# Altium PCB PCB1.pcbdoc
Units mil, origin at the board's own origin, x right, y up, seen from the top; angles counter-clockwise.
Board outline 1259.84 x 1771.65 mil, 2 copper layers (Top Layer, Bottom Layer), stack 62.206 mil thick; 37 components, 23 nets, 173 pads, 119 vias.
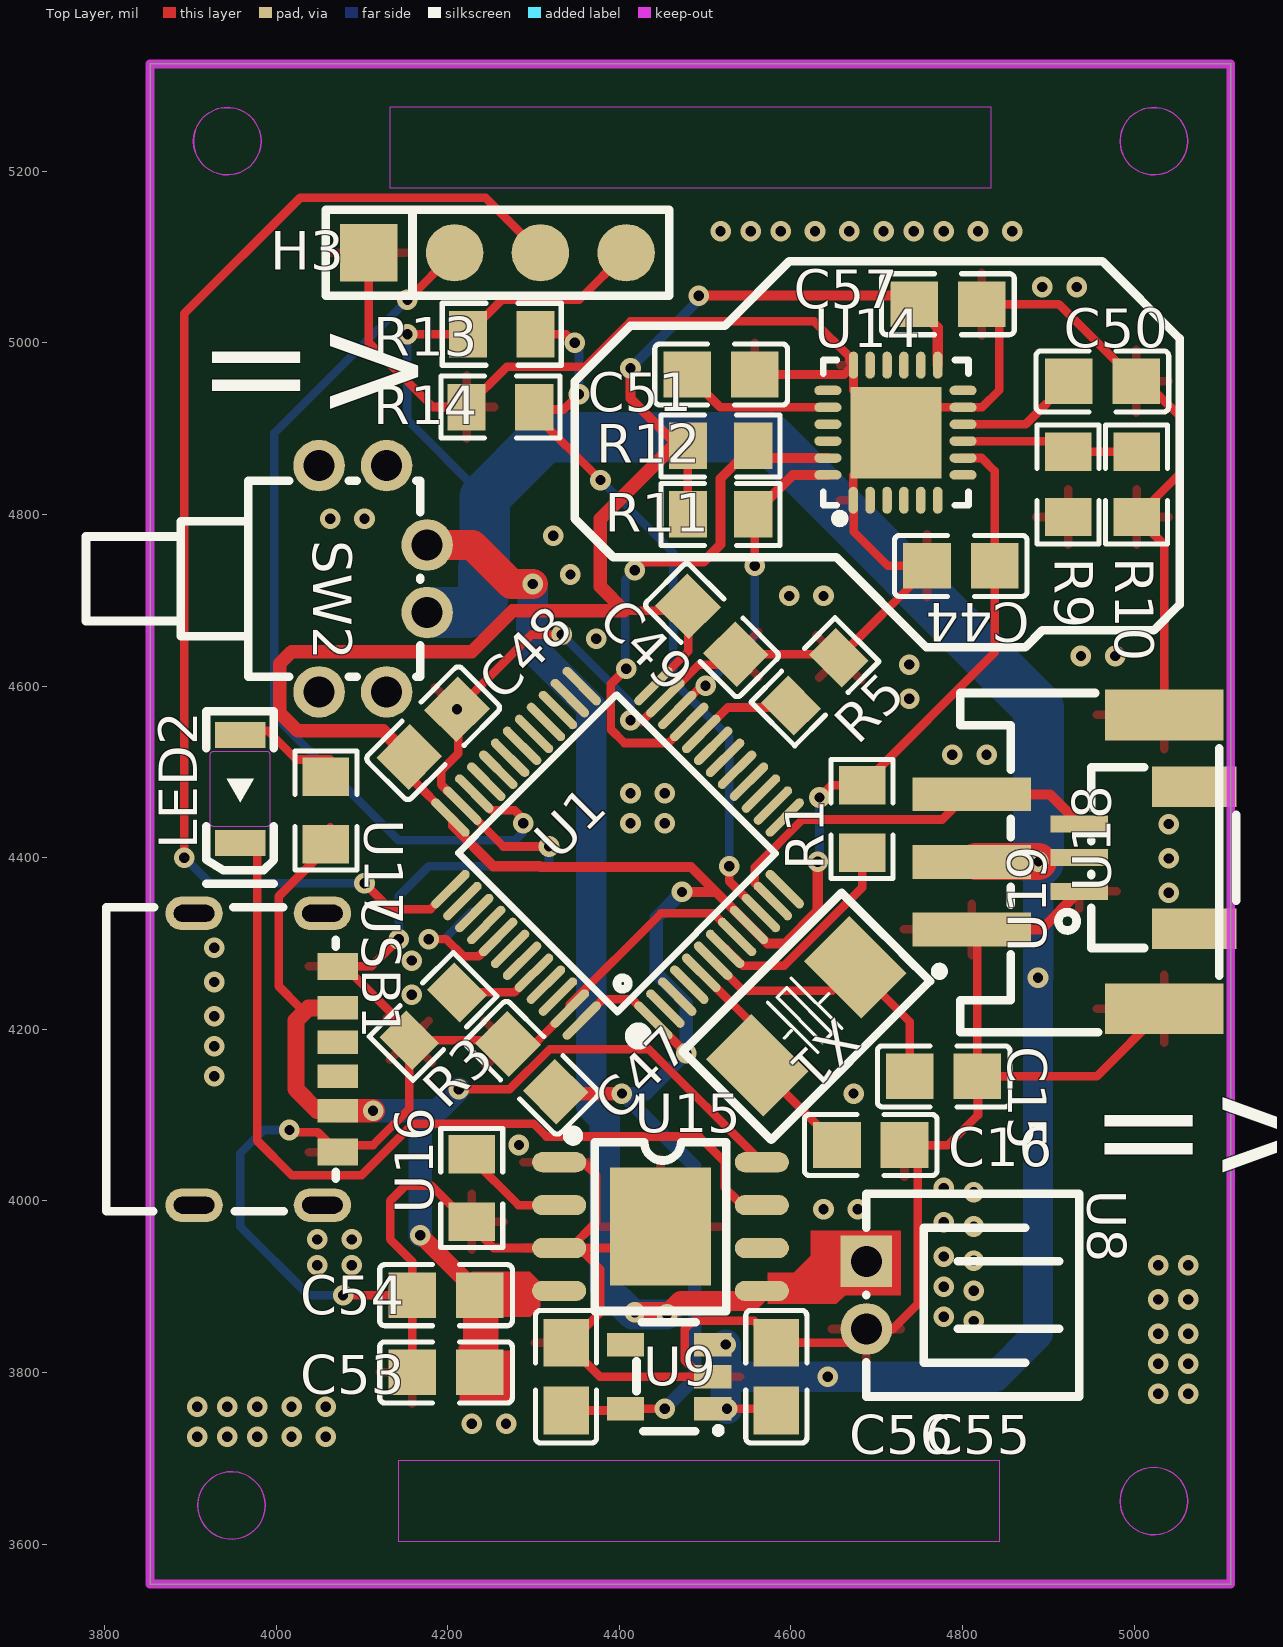
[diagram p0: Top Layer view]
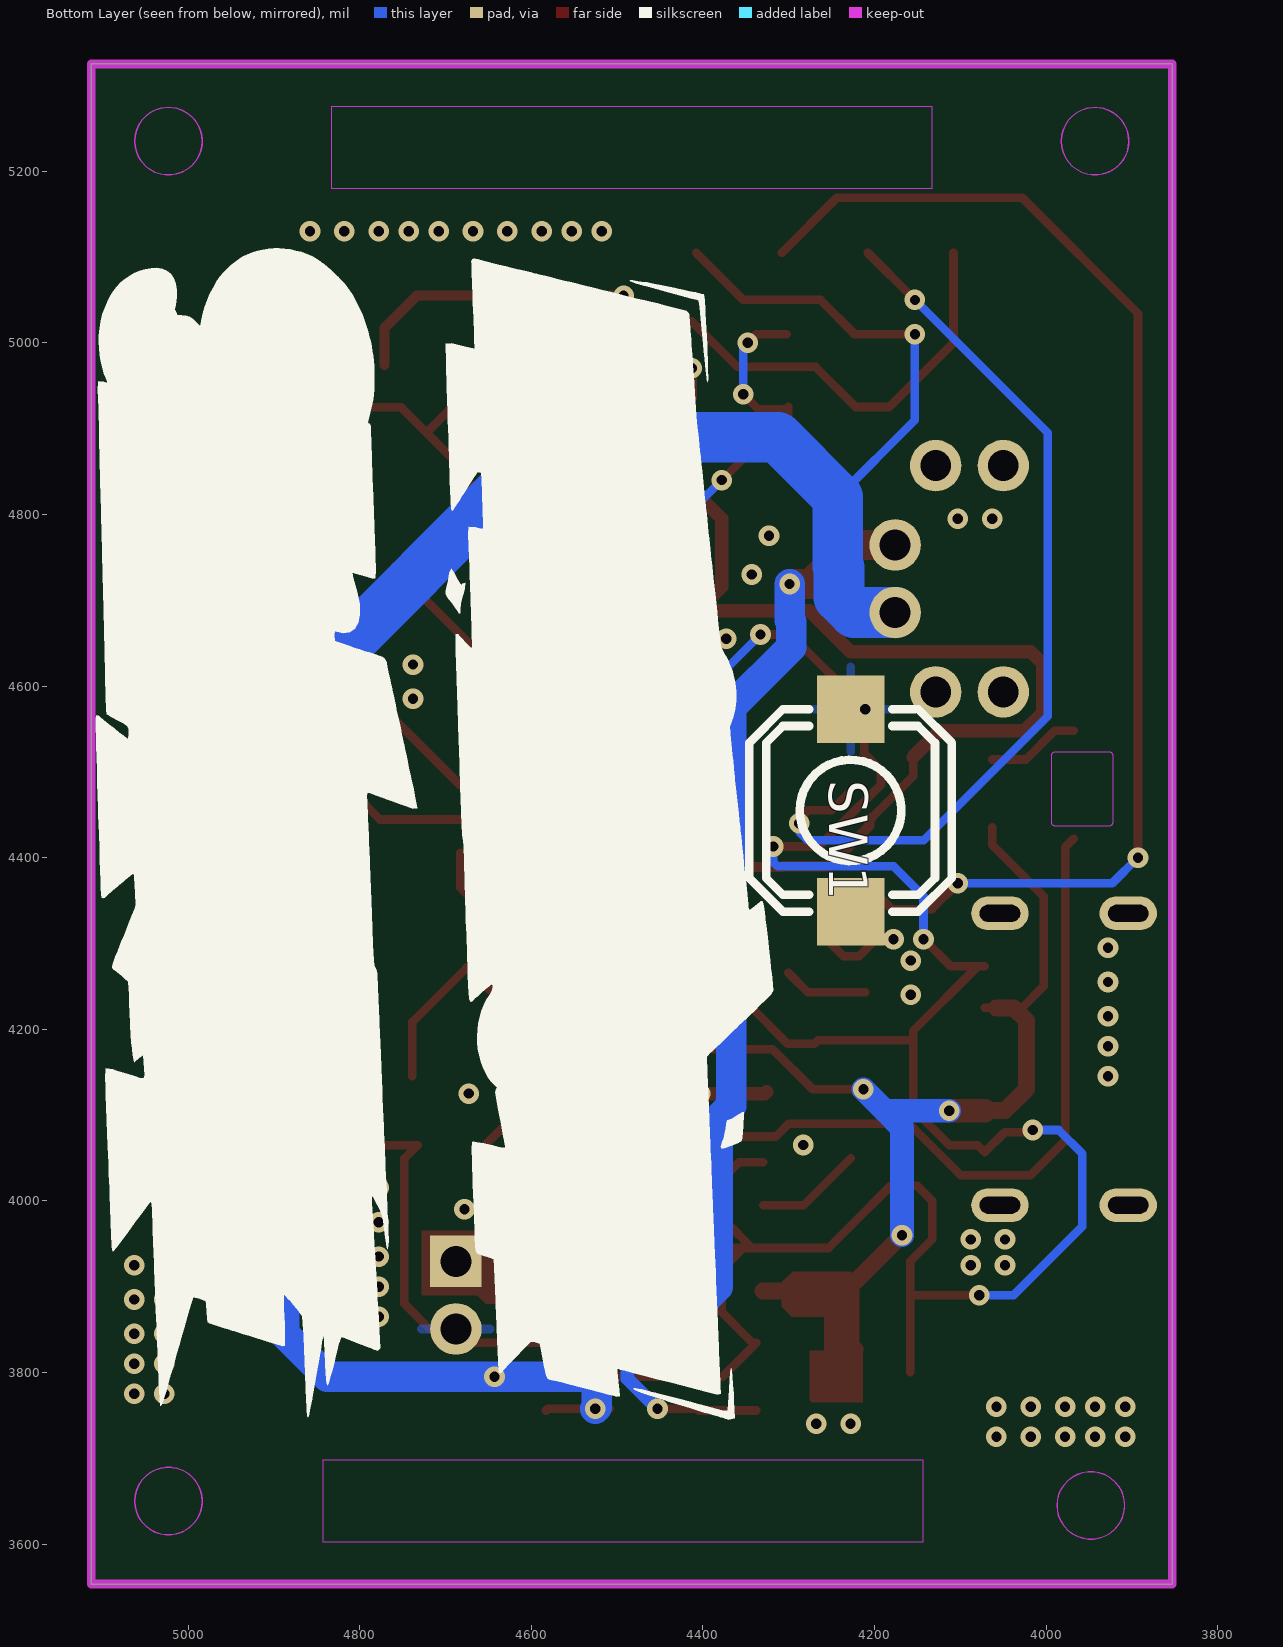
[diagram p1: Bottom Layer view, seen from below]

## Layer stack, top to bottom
Top Solder Mask Layer: solder mask 0.394, Dk 3.3
Top Layer: signal copper 1.379
Dielectric1: surface 59.449, FR4, Dk 4.5
Bottom Layer: signal copper 1.378
Bottom Solder Mask Layer: solder mask 0.394, Dk 3.3

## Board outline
3852.95,5325 5112.8,5325 5112.8,3553.35 3852.95,3553.35

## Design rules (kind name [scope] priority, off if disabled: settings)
BoardOutlineClearance copperThickness1oz [All] p0: genericclearance=10 ignorepadtopadclearanceinfootprint=FALSE except(0: Arc-SplitContinuation Track-SplitContinuation SMDPad-SplitContinuation THPad-SplitContinuation Via-SplitContinuation Fill-SplitContinuation Poly-SplitContinuation Region-SplitContinuation Text-SplitContinuation)
BoardOutlineClearance copperThickness2oz [All] p0: genericclearance=10 ignorepadtopadclearanceinfootprint=FALSE except(0: Arc-SplitContinuation Track-SplitContinuation SMDPad-SplitContinuation THPad-SplitContinuation Via-SplitContinuation Fill-SplitContinuation Poly-SplitContinuation Region-SplitContinuation Text-SplitContinuation)
BoardOutlineClearance Plane_innerPlane [All] p0: genericclearance=10 ignorepadtopadclearanceinfootprint=FALSE except(0: Arc-SplitContinuation Track-SplitContinuation SMDPad-SplitContinuation THPad-SplitContinuation Via-SplitContinuation Fill-SplitContinuation Poly-SplitContinuation Region-SplitContinuation Text-SplitContinuation)
BoardOutlineClearance Copper_copperRegion [All] p0: genericclearance=10 ignorepadtopadclearanceinfootprint=FALSE except(0: Arc-SplitContinuation Track-SplitContinuation SMDPad-SplitContinuation THPad-SplitContinuation Via-SplitContinuation Fill-SplitContinuation Poly-SplitContinuation Region-SplitContinuation Text-SplitContinuation)
BoardOutlineClearance otherClearance [All] p0: genericclearance=10 ignorepadtopadclearanceinfootprint=FALSE except(0: Arc-SplitContinuation Track-SplitContinuation SMDPad-SplitContinuation THPad-SplitContinuation Via-SplitContinuation Fill-SplitContinuation Poly-SplitContinuation Region-SplitContinuation Text-SplitContinuation)
Clearance copperThickness1oz [All] p1: gap=7 ignorepadtopadclearanceinfootprint=FALSE
Clearance copperThickness2oz [All] p1: gap=7 ignorepadtopadclearanceinfootprint=FALSE
Clearance Plane_innerPlane [All] p1: gap=7 ignorepadtopadclearanceinfootprint=FALSE
Clearance Copper_copperRegion [All] p1: gap=7 ignorepadtopadclearanceinfootprint=FALSE
Clearance otherClearance [All] p1: gap=7 ignorepadtopadclearanceinfootprint=FALSE
DiffPairsRouting differentialPair [All] p1: maxuncoupledlength=10 minlimit=6 maxlimit=Infinity mostfreqgap=6 toplayer_minwidth=5 toplayer_prefwidth=10 toplayer_maxwidth=100 bottomlayer_minwidth=5 bottomlayer_prefwidth=10 bottomlayer_maxwidth=100
PasteMaskExpansion pasteMaskExpansion [All] p1: expansion=0
PlaneConnect innerPlane [All] p1: planeconnectstyle=Relief reliefexpansion=20 reliefentries=4 reliefconductorwidth=10 reliefairgap=10
PolygonConnect copperRegion [All] p1: connectstyle=Relief reliefentries=4 reliefconductorwidth=10 polygonreliefangle="90 Angle" airgapwidth=10
RoutingVias viaSize [All] p1: viastyle="Through Hole" holewidth=12.0078 minholewidth=11.811 maxholewidth=248.0314 width=12.0078 minwidth=11.811 maxwidth=248.0314
SolderMaskExpansion solderMaskExpansion [All] p1: useseparateexpansions=TRUE expansion=2 expansionbottom=2
Width copperThickness1oz [All] p1: maxlimit=100 minlimit=5 preferedwidth=10
Width copperThickness2oz [All] p1: maxlimit=100 minlimit=8 preferedwidth=10

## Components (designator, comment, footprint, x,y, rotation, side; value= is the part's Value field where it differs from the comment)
C15 "" C0805 4777.95,4145 r180 top
C16 "" C0805 4692.95,4065 r180 top
C44 "" C0603 4797.95,4740 r180 top
C47 "" C0805 4297.95,4155 r315 top
C48 "" C0805 4182.95,4545 r225 top
C49 "" C0805 4507.95,4665 r135 top
C50 "" C0805 4962.95,4955 r180 top
C51 "" C0805 4518.62,4963.09 r0 top
C53 "" C0805 4197.95,3800 r0 top
C54 "" C0805 4197.95,3890 r0 top
C55 "" C0805 4582.95,3795 r270 top
C56 "" C0805 4337.95,3795 r270 top
C57 "" C0805 4782.95,5045 r180 top
H3 "" HDR-TH_4P-P2.54-V-M 4257.95,5105 r0 top
LED2 "" LED1206-FD_GREEN-EH 3957.95,4480 r270 top
R1 "" 0603R 4682.95,4445 r90 top
R3 "" 0603R 4182.95,4215 r225 top
R5 "" 0603R 4627.95,4605 r45 top
R9 "" R0603 4922.95,4835 r270 top
R10 "" R0603 5002.95,4835 r270 top
R11 "" R0603 4517.95,4800 r0 top
R12 "" R0603 4517.95,4880 r0 top
R13 "" R0805 4262.95,5010 r180 top
R14 "" R0805 4261.29,4925.15 r0 top
SW1 "" SW-SMD_L6.0-W6.0-P6.00-LS6.8 4227.95,4455 r270 bottom
SW2 "" SW-TH_TK-6580A-1 4112.95,4725 r270 top
U1 "" LQFP-48_L7.0-W7.0-P0.50-LS9.0-BL 4397.95,4405 r45 top
U8 "" CONN-TH_2P-P2.00_GP01-2001WR-2P 4687.95,3890 r270 top
U9 "" TSOT-23-5_L2.9-W1.6-P0.95-LS2.8-BR 4457.95,3795 r0 top
U14 "" QFN-24_L4.0-W4.0-P0.50-BL-EP2.7 4721.79,4895.24 r0 top
U15 "" SOP-8_L4.9-W3.9-P1.27-LS6.0-TL-EP 4447.95,3970 r0 top
U16 "" R0805 4227.95,4015 r90 top
U17 "" R0805 4057.95,4455 r90 top
U18 "" CONN-SMD_3P-P2.00_XUNPU_WAFER-PH2.0-3PWB 4922.95,4395 r90 top
U19 "" CONN-SMD_3P-P1.00_WAFER-SH1.0-3PWB 5002.95,4400 r90 top
USB1 "" TYPE-C-SMD_TYPE-C-6P-073 3987.95,4165 r270 top
X1 "" OSC-SMD_L5.0-W3.2 4617.95,4215 r225 top

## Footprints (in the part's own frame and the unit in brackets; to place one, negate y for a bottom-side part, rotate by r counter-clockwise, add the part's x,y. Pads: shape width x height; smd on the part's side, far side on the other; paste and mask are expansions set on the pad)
0603R [mm]
  rect 1.133x1.377 smd: 1(-1,0) 2(1,0)
  silkscreen extent -1.76,-0.92 1.76,0.92
C0603 [mm]
  rect 1.41x1.35 smd: 1(-1,0) 2(1,0)
  silkscreen extent -1.96,-0.9 1.96,0.9
C0805 [mm]
  rect 1.41x1.35 smd: 1(-1,0) 2(1,0)
  silkscreen extent -1.96,-0.9 1.96,0.9
CONN-SMD_3P-P1.00_WAFER-SH1.0-3PWB [mm]
  rect 0.5x1.7 smd: 1(-1,1.7) 2(0,1.7) 3(1,1.7)
  rect 1.2x2.5 smd: 4(-2.1,-1.7) 5(2.1,-1.7)
  silkscreen extent -2.68,-2.95 2.67,2.32
CONN-SMD_3P-P2.00_XUNPU_WAFER-PH2.0-3PWB [mm]
  rect 1x3.5 smd: 1(-2,2.85) 2(0,2.85) 3(2,2.85)
  rect 1.5x3.5 smd: 4(4.35,-2.85) 5(-4.35,-2.85)
  silkscreen extent -5.05,-4.47 5,3.94
CONN-TH_2P-P2.00_GP01-2001WR-2P [mil]
  rect 60x60 hole 36: 1(-39.37,0)
  round 60 hole 36: 2(39.37,0)
  silkscreen extent -118,0 118,248
HDR-TH_4P-P2.54-V-M [mm]
  rect 1.7x1.7 smd: 1(-3.81,0)
  round 1.7 smd: 2(-1.27,0) 3(1.27,0) 4(3.81,0)
  silkscreen extent -5.08,-1.27 5.08,1.27
LED1206-FD_GREEN-EH [mm]
  rect 0.78x1.5 smd: 1(-1.6,0) 2(1.6,0)
  Board Outline Layer lines w0.003: 1,-0.9 0,-0.9 -1,-0.9 cw(c-1,-0.8) -1.1,-0.8 -1.1,0.8 cw(c-1,0.8) -1,0.9 1,0.9 cw(c1,0.8) 1.1,0.8 1.1,-0.8 cw(c1,-0.8) 1,-0.9
  Board Outline Layer region: 0,-0.9 1,-0.9 1.038,-0.892 1.071,-0.871 1.092,-0.838 1.1,-0.8 1.1,-0.8 1.1,0.8 1.092,0.838 1.071,0.871 1.038,0.892 1,0.9 1,0.9 -1,0.9 -1.038,0.892 -1.071,0.871 -1.092,0.838 -1.1,0.8 -1.1,0.8 -1.1,-0.8 -1.092,-0.838 -1.071,-0.871 -1.038,-0.892 -1,-0.9 -1,-0.9
  Board Outline Layer region: 0,-0.9 1,-0.9 1.038,-0.892 1.071,-0.871 1.092,-0.838 1.1,-0.8 1.1,-0.8 1.1,0.8 1.092,0.838 1.071,0.871 1.038,0.892 1,0.9 1,0.9 -1,0.9 -1.038,0.892 -1.071,0.871 -1.092,0.838 -1.1,0.8 -1.1,0.8 -1.1,-0.8 -1.092,-0.838 -1.071,-0.871 -1.038,-0.892 -1,-0.9 -1,-0.9
  silkscreen extent -2.3,-1 2.8,1
LQFP-48_L7.0-W7.0-P0.50-LS9.0-BL [mm]
  oval 0.27x1.5 smd: 1(-2.75,-4.25) 2(-2.25,-4.25) 3(-1.75,-4.25) 4(-1.25,-4.25) 5(-0.75,-4.25) 6(-0.25,-4.25) 7(0.25,-4.25) 8(0.75,-4.25) 9(1.25,-4.25) 10(1.75,-4.25) 11(2.25,-4.25) 12(2.75,-4.25) 25(2.75,4.25) 26(2.25,4.25) 27(1.75,4.25) 28(1.25,4.25) 29(0.75,4.25) 30(0.25,4.25) 31(-0.25,4.25) 32(-0.75,4.25) 33(-1.25,4.25) 34(-1.75,4.25) 35(-2.25,4.25) 36(-2.75,4.25)
  oval 1.5x0.27 smd: 13(4.25,-2.75) 14(4.25,-2.25) 15(4.25,-1.75) 16(4.25,-1.25) 17(4.25,-0.75) 18(4.25,-0.25) 19(4.25,0.25) 20(4.25,0.75) 21(4.25,1.25) 22(4.25,1.75) 23(4.25,2.25) 24(4.25,2.75) 37(-4.25,2.75) 38(-4.25,2.25) 39(-4.25,1.75) 40(-4.25,1.25) 41(-4.25,0.75) 42(-4.25,0.25) 43(-4.25,-0.25) 44(-4.25,-0.75) 45(-4.25,-1.25) 46(-4.25,-1.75) 47(-4.25,-2.25) 48(-4.25,-2.75)
  silkscreen extent -3.59,-4.46 3.3,3.34
OSC-SMD_L5.0-W3.2 [mm]
  rect 1.9x2.4 smd: 1(-2.05,0) 2(2.05,0)
  silkscreen extent -3.32,-1.85 3.33,1.85
QFN-24_L4.0-W4.0-P0.50-BL-EP2.7 [mm]
  oval 0.28x0.8 smd: 1(-1.25,-2) 2(-0.75,-2) 3(-0.25,-2) 4(0.25,-2) 5(0.75,-2) 6(1.25,-2) 13(1.25,2) 14(0.75,2) 15(0.25,2) 16(-0.25,2) 17(-0.75,2) 18(-1.242,2)
  oval 0.8x0.28 smd: 7(2,-1.25) 8(2,-0.75) 9(2,-0.25) 10(2,0.25) 11(2,0.75) 12(2,1.25) 19(-2,1.25) 20(-2,0.75) 21(-2,0.25) 22(-2,-0.25) 23(-2,-0.75) 24(-2,-1.25)
  rect 2.7x2.7 smd: 25(0.012,0)
  silkscreen extent -2.14,-2.79 2.16,2.15
R0603 [mil]
  rect 44.59x54.21 smd: 1(-38.04,0) 2(38.04,0)
  silkscreen extent -69,-36 69,36
R0805 [mm]
  rect 1.133x1.377 smd: 1(-1,0) 2(1,0)
  silkscreen extent -1.76,-0.92 1.76,0.92
SOP-8_L4.9-W3.9-P1.27-LS6.0-TL-EP [mm]
  oval 1.6x0.6 smd: 1(-3,1.905) 2(-3,0.635) 3(-3,-0.635) 4(-3,-1.905) 5(3,-1.905) 6(3,-0.635) 7(3,0.635) 8(3,1.905)
  rect 3x3.5 smd: 9(0,0)
  silkscreen extent -2.74,-2.5 1.95,2.84
SW-SMD_L6.0-W6.0-P6.00-LS6.8 [mm]
  rect 2x2 smd: 1(-3,0) 2(3,0)
  silkscreen extent -3,-3 3,3
SW-TH_TK-6580A-1 [mil]
  round 60 hole 36: 1(131.89,-62.99) 2(131.89,15.75) 3(-131.89,-62.99) 4(-131.89,15.75) 5(39.37,62.99) 6(-39.37,62.99)
  silkscreen extent -114,-335 114,55
TSOT-23-5_L2.9-W1.6-P0.95-LS2.8-BR [mm]
  rect 1.1x0.7 smd: 1(1.294,-0.951) 2(1.294,-0.001) 3(1.294,0.951) 4(-1.294,0.951) 5(-1.294,-0.949)
  silkscreen extent -0.97,-1.65 1.52,1.61
TYPE-C-SMD_TYPE-C-6P-073 [mm]
  oval 1x1.7 hole 0.5 slot 1.2 at 90 deg: 7(-4.32,1.675) 7(-4.32,-2.125) 7(4.32,1.675) 7(4.32,-2.125)
  rect 0.7x1.2 smd: A5(-0.5,2.125) A9(1.52,2.125) B5(0.5,2.125) B9(-1.52,2.125)
  rect 0.8x1.2 smd: A12(2.75,2.125) B12(-2.75,2.125)
  silkscreen extent -4.5,-4.73 4.5,2.08

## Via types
v1: diameter 24.02, hole 12.01, Top Layer to Bottom Layer, 119 vias

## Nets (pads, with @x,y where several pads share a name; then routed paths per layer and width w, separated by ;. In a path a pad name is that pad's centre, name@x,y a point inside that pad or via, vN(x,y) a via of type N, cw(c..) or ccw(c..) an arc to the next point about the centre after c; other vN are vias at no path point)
$1N2051: C15.2 U1.6 X1.1 | length 344.7
  Top Layer w10: U1.6 4544.03,4245 4647.95,4245 X1.1 4738.58,4208.51 C15.2
$1N2052: C16.2 U1.5 X1.2 | length 266.3
  Top Layer w10: U1.5 4560.88,4200.31 X1.2 4653.58,4065.23 C16.2
$1N3067: U1.11 U18.3 U19.3 | length 475.8
  Top Layer w10: U1.11 4578.69,4349.32 4557.95,4370.06 4557.95,4388.83 4613.54,4444.41 4776.42,4444.41 4805.75,4473.74 U18.3
  Top Layer w11.81: U18.3 4901.65,4473.74 U19.3
$1N4185: C51.1 U14.20 | length 179.7
  Top Layer w10: C51.1 4517.57,4924.77 U14.20
$1N4192: C50.2 U14.10 | length 143.7
  Top Layer w10: U14.10 4873.67,4905.08 C50.2
$1N4205: R9.1 R10.1 U14.9 | length 207.5
  Top Layer w10: U14.9 4910.59,4885.4 R9.1 R10.1
$1N6407: U15.2 U16.2 | length 124.4
  Top Layer w10: U16.2@4227.95,4049.37 4282.32,3995 U15.2
$1N6763: LED2.1 U17.2 | length 108.9
  Top Layer w10: LED2.1@3967.95,4547.99 3989.96,4547.99 4023.58,4514.37 U17.2@4062.95,4514.37
$1N6769: LED2.2 U15.7 | length 1042.6
  Top Layer w10: LED2.2@3967.95,4422.01 3977.95,4412.01 3977.95,4070 4017.96,4030 4099.79,4030 4159.79,4090 4299.96,4090 4314.96,4075 4492.95,4075 4522.95,4045 4522.95,4015 4537.95,4000 4561.06,4000 U15.7
+5V: C55.2 H3.4 R13.2 SW2.5 U9.1 U9.3 U18.2 U19.2 | length 2870.9
  Top Layer w10: v1(4152.95,5010) R13.2 4223.58,5010.63 4262.95,5050 4352.95,5050 H3.4 ; U9.1 v1(4525.51,3757.56) 4581.03,3757.56 C55.2
  Top Layer w15.75: U9.3 v1(4523.9,3832.44)
  Top Layer w43.31: U18.2@4815.75,4395.42 v1(4888.43,4395.42)
  Bottom Layer w10: v1(4152.95,5010) 4152.95,4910 4242.95,4820
  Bottom Layer w35.43: v1(4523.9,3832.44) 4523.9,3797.88 ; v1(4525.51,3757.56) 4523.9,3759.17 4523.9,3797.88 ; v1(4888.43,4395.42) 4888.43,4260.47 v1(4887.95,4260) 4887.95,3845 4837.95,3795 v1(4642.95,3795) 4526.78,3795 4523.9,3797.88
  Bottom Layer w59.06: SW2.5 4223.58,4685.63 4241.45,4703.5 4241.45,4737.88 4242.95,4739.38 4242.95,4820 4312.95,4890 4572.95,4890 4888.43,4574.53 v1(4888.43,4395.42)
ADC: R13.1 R14.2 U1.10 | length 870.6
  Top Layer w10: R14.2 R14.2@4300.66,4922.29 ; R13.1 4337.95,5010 v1(4347.95,5000) ; v1(4352.95,4940.15) 4335.1,4922.29 R14.2@4300.66,4922.29 ; v1(4377.95,4840) 4300.66,4917.29 R14.2@4300.66,4922.29 ; v1(4527.95,4390) 4527.95,4372.44 U1.10
  Bottom Layer w10: v1(4347.95,5000) 4352.95,4995 v1(4352.95,4940.15) ; v1(4377.95,4840) 4462.95,4755 4462.95,4605 4527.95,4540 v1(4527.95,4390)
BAT: SW2.6 U8.1 U15.5 | length 1379.7
  Top Layer w10: U15.5 4653.58,3895 U8.1
  Top Layer w23.62: v1(4417.95,3870) 4452.95,3870 v1(4455.45,3867.5) 4471.26,3883.31 4554.37,3883.31 U15.5
  Top Layer w35.43: SW2.6 4228.58,4764.37 4274.05,4718.9 v1(4299.05,4718.9)
  Bottom Layer w35.43: v1(4299.05,4718.9) 4299.05,4676.6 4297.24,4674.79 4297.24,4645.21 4367.24,4575.21 4367.24,4110.21 4382.95,4094.5 4382.95,3900 4415.45,3867.5 v1(4455.45,3867.5)
BOOT0: R3.1 U1.44 | length 99.2
  Top Layer w10: R3.1 4277.55,4242.84 U1.44
BOOT1: R5.1 U1.20 | length 118.4
  Top Layer w10: U1.20 4526.19,4575 4597.95,4575 R5.1
CLK: H3.3 U1.37 | length 1476.1
  Top Layer w10: v1(3892.95,4400) 3892.95,5034.02 4027.95,5169.02 4243.94,5169.02 H3.3 ; v1(4102.95,4370) 4132.95,4340 4179.84,4340 U1.37
  Bottom Layer w10: v1(3892.95,4400) 3922.95,4370 v1(4102.95,4370)
DIO: H3.2 U1.34 | length 1065.5
  Top Layer w10: v1(4152.95,5050) H3.2 ; U1.34 4250.51,4455 4277.95,4455 4287.95,4445 v1(4287.95,4440)
  Bottom Layer w10: v1(4152.95,5050) 3997.95,4895 3997.95,4565 4142.95,4420 4277.95,4420 4287.95,4430 v1(4287.95,4440)
GND: C15.1 C16.1 C44.2 C47.1 C48.1 C49.1 C50.1 C51.2 C53.1 C54.1 C55.1 C56.1 C57.1 H3.1 R3.2 R5.2 R9.2 R10.2 R14.1 SW1.1 U1.8 U1.23 U1.35 U1.47 U8.2 U9.2 U14.1 U14.11 U14.18 U14.25 U15.1 U15.3 U15.9 U16.1 U18.1 U18.4 U18.5 U19.1 USB1.A12 USB1.B12 | length 6990.3
  Top Layer w10: v1(4015.45,4082.5) 4017.95,4080 4048.35,4080 USB1.A12 4079.89,4065 4112.95,4065 4155.11,4107.16 R3.2 ; USB1.B12 USB1.B12@4079.69,4273.27 ; v1(4077.95,3890) C54.1 ; H3.1 4107.95,5000 4182.81,4925.15 R14.1 4268.68,4971.91 4359.86,4971.91 4412.95,5025 4626.87,5025 4667.89,4983.98 4667.89,4978.98 U14.18 ; v1(4142.95,4305) 4111.22,4273.27 USB1.B12@4079.69,4273.27 ; C53.1 C54.1 ; U1.35@4216.78,4460.68 4192.5,4484.96 4192.5,4501.43 4212,4520.93 4212,4566.63 4210.79,4567.84 v1(4210.79,4572.84) 4297.95,4660 v1(4332.95,4660) ; U1.35 4217.27,4460.68 4264.96,4412.99 v1(4317.95,4412.99) ; U15.1 4357.95,4045 4372.95,4030 4372.95,3975 U15.3@4342.95,3945 ; v1(4412.95,4560) 4427.68,4560 U1.23 4492.68,4625 4523.63,4625 C49.1 4651.47,4637.16 R5.2 4758.58,4735.63 C44.2 4712.95,4740 4672.95,4780 4672.95,4816.13 U14.1 4672.58,4845.54 U14.25 ; U15.9 4422.95,3945 U15.3@4352.95,3945 ; U9.2 U9.2@4495.41,3794.96 ; U1.8 4509.71,4335 4448.43,4335 4342.27,4228.84 U1.47 4301.06,4182.84 C47.1 4265.79,4187.16 R3.2 ; C51.2 4661.99,4963.09 U14.18 ; U18.1 4817.32,4309.69 C15.1 ; C57.1 C57.1@4826.17,5045 ; U18.5 4956.42,4145 C15.1 ; U18.4 5035.16,4764.76 R10.2 5052.95,4846.96 5052.95,4915 5042.95,4925 5042.32,4925 5012.32,4955 C50.1 4912.32,5045 C57.1@4826.17,5045 ; USB1.B12@4079.69,4273.27 4155.11,4197.84 R3.2 ; C54.1 4158.58,3929.37 4132.95,3955 4132.95,4000 4150.45,4017.5 4181.08,4017.5 4227.95,3970.63 4253.58,3945 U15.3 U15.3@4342.95,3945 ; U15.3@4342.95,3945 U15.3@4352.95,3945 ; U15.3@4352.95,3945 4377.95,3920 4377.95,3870 4342.32,3834.37 C56.1 4377.37,3794.96 U9.2@4495.41,3794.96 ; U9.2@4495.41,3794.96 4476.26,3814.11 4476.26,3850.77 4482.69,3857.2 4483.46,3857.2 4486.26,3860 4557.32,3860 C55.1 4671.69,3834.37 U8.2 4718.58,3850.63 4747.95,3880 4747.95,4049.37 C16.1 4782.95,4065 4817.95,4100 4817.95,4144.37 C15.1 ; U14.18 4672.89,4944.63 U14.25 ; U14.25 4751.81,4924.77 U14.11 4822.73,4924.77 4842.95,4945 4842.95,5028.22 C57.1@4826.17,5045
  Top Layer w11.81: U18.1 4891.66,4316.26 U19.1
  Bottom Layer w10: v1(4015.45,4082.5) 3985.45,4082.5 3957.95,4055 3957.95,3970 4037.95,3890 v1(4077.95,3890) ; v1(4142.95,4305) 4142.95,4355 4177.95,4390 4312.95,4390 4317.95,4395 v1(4317.95,4412.99) ; v1(4332.95,4660) 4412.95,4580 v1(4412.95,4560)
  other v1: 3907.95,3725 3942.95,3725 3977.95,3725 4017.95,3725 4057.95,3725 4227.95,3740 4267.95,3740 3907.95,3760 3942.95,3760 3977.95,3760 4017.95,3760 4057.95,3760 5027.95,3775 5062.95,3775 5027.95,3810 5062.95,3810 5027.95,3845 5062.95,3845 4812.95,3860 4777.95,3865 5027.95,3885 5062.95,3885 4812.95,3895 4777.95,3900 4047.95,3925 4087.95,3925 5027.95,3925 5062.95,3925 4812.95,3930 4777.95,3935 4047.95,3955 4087.95,3955 4812.95,3970 4777.95,3975 4637.95,3990 4677.95,3990 4812.95,4010 4777.95,4015 4282.95,4065 4672.95,4125 3927.95,4145 3927.95,4180 3927.95,4215 4157.95,4240 3927.95,4255 4157.95,4280 3927.95,4295 5040.46,4359.06 5040.46,4399.06 5040.46,4439.06 4412.95,4440 4452.95,4440 4412.95,4475 4452.95,4475 4787.95,4520 4827.95,4520 4737.95,4585 4737.95,4625 4937.95,4635 4977.95,4635 4372.95,4655 4597.95,4705 4637.95,4705 4342.95,4730 4322.95,4775 4062.95,4795 4102.95,4795 4892.95,5065 4932.95,5065 4517.95,5130 4552.95,5130 4587.95,5130 4627.95,5130 4667.95,5130 4707.95,5130 4742.95,5130 4777.95,5130 4817.95,5130 4857.95,5130
IIC_SCL: R12.2 U1.21 U14.23 | length 642.5
  Top Layer w10: v1(4407.95,4620) 4389.96,4602.01 4389.96,4549.61 4405.96,4533.61 4457.17,4533.61 4481.46,4557.9 U1.21
  Top Layer w11.81: v1(4417.95,4735) 4427.95,4745 4497.95,4745 4517.95,4765 4517.95,4841.96 R12.2 4570.28,4865.71 U14.23
  Bottom Layer w10: v1(4407.95,4620) 4406.77,4621.18 4406.77,4723.82 v1(4417.95,4735)
IIC_SDA: R11.2 U1.22 U14.24 | length 381.1
  Top Layer w10: U1.22 4470.04,4574.53 4470.48,4574.53 4500.45,4604.51 v1@4500.45,4600.25 ; R11.2 4557.95,4798.04 v1(4557.95,4740)
  Top Layer w11.81: R11.2 4602.03,4846.03 U14.24
  Bottom Layer w10: v1(4500.45,4600.25) 4557.95,4657.75 v1(4557.95,4740)
KEY: SW1.2 U1.41 | length 161.6
  Top Layer w10: v1(4177.95,4305) 4197.95,4305 4217.95,4285 4236.18,4285 U1.41
  Bottom Layer w10: v1(4177.95,4305) 4196.06,4305 SW1.2
NRST: R1.1 U1.7 | length 246.1
  Top Layer w10: U1.7 4524.31,4293.64 4543.8,4274.15 4592.1,4274.15 4682.95,4365 R1.1
VCC: C44.1 C47.2 C48.2 C49.2 C56.2 C57.2 R1.2 R11.1 R12.1 U1.1 U1.9 U1.24 U1.36 U1.48 U9.5 U14.8 U14.13 | length 4124
  Top Layer w10: C48.2 4155.11,4494.72 U1.36 ; C56.2 4405,3755.63 U9.5 v1(4452.95,3757.64) ; U1.48 4381.06,4235 4414.83,4235 U1.1 v1(4477.95,4171.88) ; 4405.64,4687.84 4470.11,4687.84 4475.11,4692.84 C49.2 4480.11,4640.28 U1.24 ; R12.1@4463.13,4880 R12.1 R11.1 ; v1(4633.25,4470) 4647.62,4484.37 R1.2 4837.32,4638.74 C44.1 4837.32,4850.63 4822.24,4865.71 U14.8
  Top Layer w11.81: U1.36 4206.2,4443.63 4206.2,4436.75 4252.95,4390 4307.15,4390 4308.05,4389.09 4483.45,4389.09 4512.54,4360 ; v1(4412.95,4970.44) 4412.95,4935.18 4463.13,4885 R12.1@4463.13,4880 ; v1(4472.95,4360) 4512.54,4360 ; v1(4492.51,5055) 4733.58,5055 C57.2 4771,5017.59 U14.13 ; v1(4631.24,4395) 4631.24,4338.29 4592.95,4300 4572.54,4300 U1.9 4512.54,4360
  Top Layer w15.75: C48.2 4124.63,4547.65 4025.3,4547.65 4003.98,4568.97 4003.98,4626.03 4017.95,4640 4227.95,4640 4275.79,4687.84 4405.64,4687.84 4377.95,4715.52 4377.95,4794.82 R12.1@4463.13,4880 ; C47.2 4327.95,4125 v1(4402.95,4125)
  Bottom Layer w10: v1(4631.24,4395) 4633.25,4397.01 v1(4633.25,4470)
  Bottom Layer w11.81: v1(4412.95,4970.44) 4492.51,5050 v1(4492.51,5055)
  Bottom Layer w15.75: v1(4452.95,3757.64) 4487.95,3792.64 4487.95,4040 v1(4402.95,4125) 4431.07,4125 v1(4477.95,4171.88) 4477.95,4230 4442.95,4265 4442.95,4330 v1(4472.95,4360)
VIN: C53.2 C54.2 U15.4 U15.8 U17.1 USB1.A9 USB1.B9 | length 1464.1
  Top Layer w9.84: v1(4212.95,4130) 4272.06,4130 4318.63,4176.56 4434.5,4176.56 U15.8
  Top Layer w10: 4037.79,4224.84 4028.11,4224.84 4002.95,4250 4002.95,4355 4062.95,4415 U17.1@4062.95,4435.63 ; USB1.B9@4058.11,4224.84 USB1.B9
  Top Layer w19.68: USB1.B9@4058.11,4224.84 4037.79,4224.84 4022.95,4210 4022.95,4130 4047.79,4105.16 USB1.A9 ; v1(4167.95,3960) C54.2@4237.32,3890.63 ; C53.2 C54.2 4242.32,3895 U15.4
  Top Layer w27.56: USB1.A9 4071.78,4105 v1(4112.95,4105)
  Bottom Layer w27.56: v1(4112.95,4105) 4187.95,4105 ; v1(4167.95,3960) 4167.95,4085 4187.95,4105 ; v1(4212.95,4130) 4187.95,4105
pads on no net: SW2.1 SW2.2 SW2.3 SW2.4 U1.2 U1.3 U1.4 U1.12 U1.13 U1.14 U1.15 U1.16 U1.17 U1.18 U1.19 U1.25 U1.26 U1.27 U1.28 U1.29 U1.30 U1.31 U1.32 U1.33 U1.38 U1.39 U1.40 U1.42 U1.43 U1.45 U1.46 U9.4 U14.2 U14.3 U14.4 U14.5 U14.6 U14.7 U14.12 U14.14 U14.15 U14.16 U14.17 U14.19 U14.21 U14.22 U15.6 U19.4 U19.5 USB1.7 USB1.A5 USB1.B5

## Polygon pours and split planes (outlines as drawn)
GND on Top Layer (solid, remove dead copper, pour order 0): 3647.95,5565 5367.95,5565 5367.95,3355 3647.95,3355
GND on Bottom Layer (solid, remove dead copper, pour order 2): 3322.95,5815 5622.95,5815 5622.95,3115 3322.95,3115

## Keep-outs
Board Outline Layer:
  region: 3982.32,5235 cw(c3942.95,5235) 3903.58,5235 cw(c3942.95,5235)
  circle w0.1: c3942.95,5235 r39.37
  region: 3982.32,5235 cw(c3942.95,5235) 3903.58,5235 cw(c3942.95,5235)
  region: 4132.95,5275 4832.95,5275 4832.95,5180 4132.95,5180
  region: 4132.95,5275 4832.95,5275 4832.95,5180 4132.95,5180
  region: 4142.95,3697.5 4842.95,3697.5 4842.95,3602.5 4142.95,3602.5
  region: 4142.95,3697.5 4842.95,3697.5 4842.95,3602.5 4142.95,3602.5
  region: 5062.32,5235 cw(c5022.95,5235) 4983.58,5235 cw(c5022.95,5235)
  circle w0.1: c5022.95,5235 r39.37
  region: 5062.32,5235 cw(c5022.95,5235) 4983.58,5235 cw(c5022.95,5235)
  region: 5062.32,3650 cw(c5022.95,3650) 4983.58,3650 cw(c5022.95,3650)
  circle w0.1: c5022.95,3650 r39.37
  region: 5062.32,3650 cw(c5022.95,3650) 4983.58,3650 cw(c5022.95,3650)
  region: 3987.32,3645 cw(c3947.95,3645) 3908.58,3645 cw(c3947.95,3645)
  circle w0.1: c3947.95,3645 r39.37
  region: 3987.32,3645 cw(c3947.95,3645) 3908.58,3645 cw(c3947.95,3645)
  lines w0.1: 4132.95,5180 4832.95,5180 4832.95,5275 4132.95,5275 4132.95,5180 ; 4142.95,3602.5 4842.95,3602.5 4842.95,3697.5 4142.95,3697.5 4142.95,3602.5
  lines w10: 3852.95,3553.35 5112.8,3553.35 5112.8,5325 3852.95,5325 3852.95,3553.35

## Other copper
Top Layer:
  region net VIN: 4227.95,3917.61 4295.34,3917.61 4307.95,3905 4307.95,3876.55 4296.4,3865 4258.67,3865 4258.67,3825 4275.26,3825 4275.26,3767.31 4272.95,3765 4213.75,3765 4213.75,3824.2 4212.95,3825 4212.95,3830 4217.95,3835 4217.95,3907.61
  region net BAT: 4727.95,3965 4727.95,3890.03 4662.98,3890.03 4652.95,3880 4572.95,3880 4572.95,3916.2 4602.95,3916.2 4622.95,3936.2 4622.95,3965

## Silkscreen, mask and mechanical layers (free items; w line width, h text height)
Top Silkscreen Layer:
  lines w10: 4347.95,4795 4392.95,4750 4652.95,4750 4757.95,4645 4872.95,4645 4892.95,4665 5022.95,4665 5052.95,4695 5052.95,5005 4962.95,5095 4597.95,5095 4522.95,5020 4412.95,5020 4347.95,4955 4347.95,4795
  text "=>" at 3907.95,4915 h120
  text "=>" at 4947.95,4025 h120
Bottom Silkscreen Layer:
  drawing of 51 lines, arcs and shapes, not listed
Mechanical Layer:
  circle w0.1: c3942.95,5235 r39.37
  circle w0.1: c5022.95,5235 r39.37
  circle w0.1: c5022.95,3650 r39.37
  circle w0.1: c3947.95,3645 r39.37
  lines w0.1: 4132.95,5180 4832.95,5180 4832.95,5275 4132.95,5275 4132.95,5180 ; 4142.95,3602.5 4842.95,3602.5 4842.95,3697.5 4142.95,3697.5 4142.95,3602.5
3D Shell Outline Layer:
  pour cut-out: 5487.95,4525 5645.43,4525 5645.43,4288.78 5487.95,4288.78
  pour cut-out: 3255.91,4725 cw(c3127.95,4725) 3000,4725 cw(c3127.95,4725)
  pour cut-out: 3167.01,4345 3188.9,4345 cw(c3188.9,4285.94) 3247.95,4285.94 3247.95,4039.06 cw(c3188.9,4039.06) 3188.9,3980 3167.01,3980 cw(c3167.01,4039.06) 3107.95,4039.06 3107.95,4285.94 cw(c3167.01,4285.94)
  pour cut-out: 4127.95,5855 4852.95,5855 4852.95,5765 4127.95,5765
  pour cut-out: 4115.45,3090 4840.45,3090 4840.45,3000 4115.45,3000
  pour cut-out: 3802.95,5380 5176.97,5380 5176.97,3494.17 3802.95,3494.17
